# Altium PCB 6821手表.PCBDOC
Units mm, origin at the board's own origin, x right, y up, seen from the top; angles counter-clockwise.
Board outline 79.43 x 61.75 mm, 2 copper layers (Top Layer, Bottom Layer); 27 components, 27 nets, 80 pads, 76 vias.
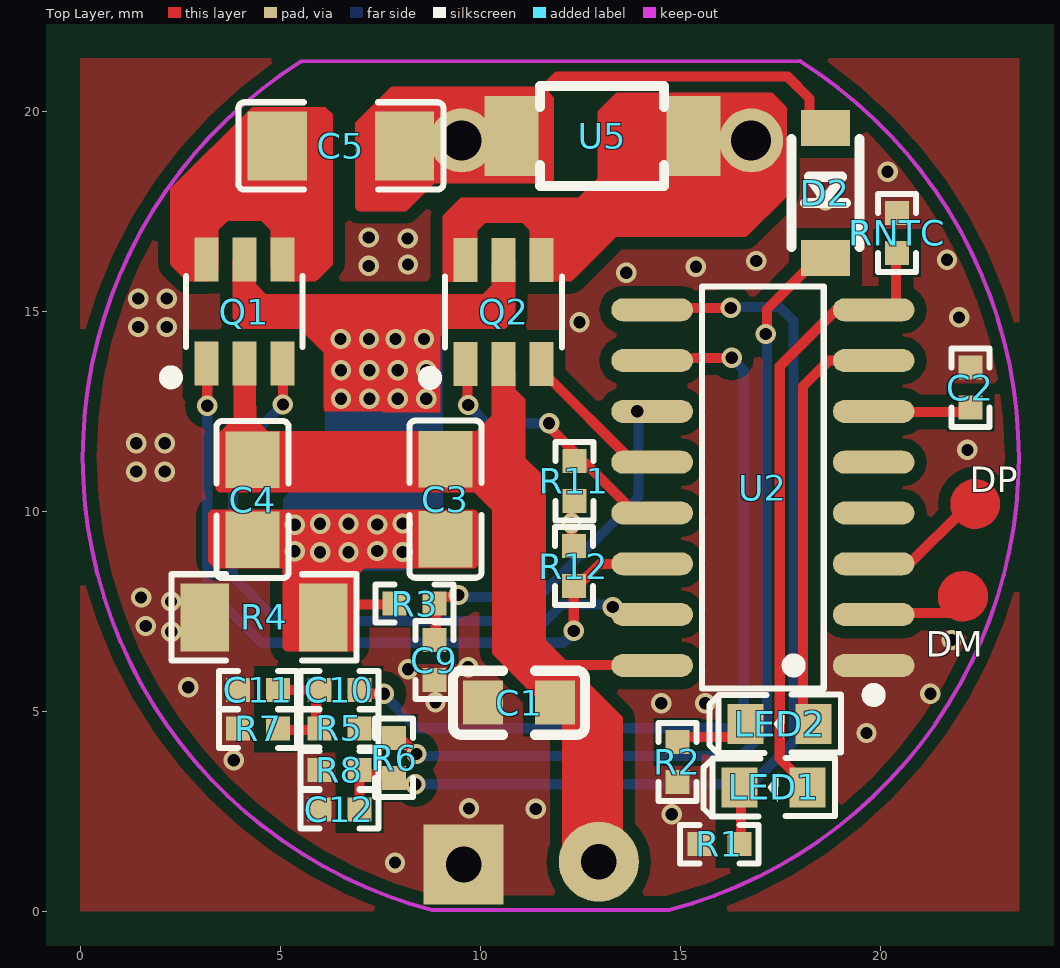
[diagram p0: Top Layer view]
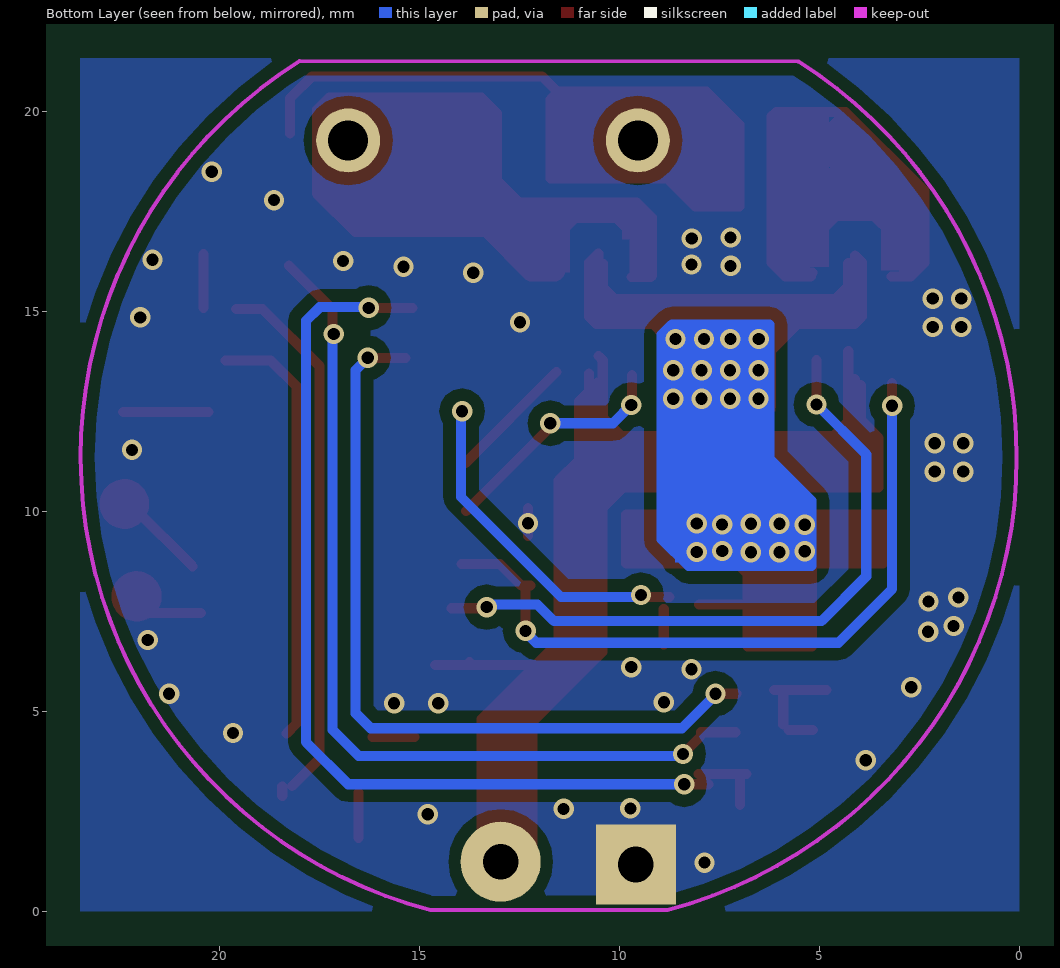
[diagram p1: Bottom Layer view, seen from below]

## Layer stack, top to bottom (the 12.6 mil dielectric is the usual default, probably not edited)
Top Layer: signal copper 0.0356
Dielectric: dielectric 0.32, FR-4, Dk 4.8
Bottom Layer: signal copper 0.0356

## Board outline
55.912,-11.556 -23.514,-11.556 -23.514,50.191 55.912,50.191

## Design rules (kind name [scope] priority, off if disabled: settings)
Clearance [All] p1: gap=0.305
ComponentClearance [All] p1: gap=0.254 collisioncheckmode=3 verticalgap=0.254
PlaneClearance [All] p1: clearance=0
PlaneConnect [All] p1: planeconnectstyle=Direct reliefexpansion=0.508 reliefentries=2 reliefconductorwidth=0.254 reliefairgap=0.254
PolygonConnect [All] p1: connectstyle=Direct reliefconductorwidth=0.254 reliefentries=2 polygonreliefangle="90 Angle"
RoutingVias [All] p1: holewidth=0.711 width=1.27 viastyle="Through Hole" minholewidth=0.711 minwidth=1.27 maxholewidth=0.711 maxwidth=1.27
SolderMaskExpansion [All] p1: expansion=0.102
TestPointUsage [All] p1: valid=0 allowmultiple=FALSE
Testpoint [All] p1: side=15 testpointundercomponent=TRUE minsize=1.016 maxsize=2.54 preferedsize=1.524 minholesize=0 maxholesize=1.016 preferedholesize=0.813 testpointgrid=0.025 style=1023 order=0123456789
Width [All] p1: maxlimit=0.254 minlimit=0.254 preferedwidth=0.254
16 further rules are at their usual default settings.

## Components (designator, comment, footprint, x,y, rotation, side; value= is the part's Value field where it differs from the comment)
C1 "10uF" C0603#1 10.966,5.213 r180 top
C2 "2.2uF" C0603#2 22.251,13.089 r270 top
C3 "22uF" C0805 9.127,10.299 r90 top (schematic designator C9)
C4 "22uF" C0805 4.304,10.289 r90 top (schematic designator C9)
C5 "68nF/NPO" C1206 6.511,19.131 r180 top (schematic designator C11)
C9 "10nF" C0603#2 8.852,6.277 r90 top (schematic designator C12)
C10 "10nF" C0603#2 6.475,5.533 r0 top
C11 "10nF" C0603#2 4.44,5.53 r0 top
C12 "10nF" C0603#2 6.475,2.548 r180 top
D2 "IN5819" SOD-123_L2.7-W1.6-LS3.7-R-RD 18.627,17.955 r90 top
LED1 "R" LED0603_RED 17.328,3.097 r180 top
LED2 "B" LED0603_GREEN 17.478,4.682 r180 top
Q1 "AP10G02" PCBComponent_1#1 4.098,14.992 r0 top
Q2 "AP10G02" PCBComponent_1#1 10.578,14.981 r0 top
R1 "1K" C0603#2 15.972,1.674 r0 top
R2 "1K" C0603#2 14.923,3.732 r90 top
R3 "3.3k" C0603#2 8.355,7.689 r0 top (schematic designator R9)
R4 "20mR" R1206 4.591,7.345 r180 top (schematic designator R10)
R5 "3.3K" C0603#2 6.475,4.57 r0 top
R6 "33K" C0603#2 7.841,3.833 r90 top
R7 "33K" C0603#2 4.44,4.562 r0 top
R8 "3.3k" C0603#2 6.475,3.534 r0 top
R11 "3.3K" C0603#2 12.348,10.749 r90 top
R12 "3.3K" C0603#2 12.337,8.629 r90 top
RNTC "100k/B3950" C0603#2 20.417,16.958 r270 top (schematic designator R1)
U2 "IP6821" SOP-16_L9.9-W3.9-P1.27-LS6.0-BL 17.062,10.59 r90 top (schematic designator U1)
U5 "XianQuan" PCBComponent_1#2 13.051,19.38 r0 top

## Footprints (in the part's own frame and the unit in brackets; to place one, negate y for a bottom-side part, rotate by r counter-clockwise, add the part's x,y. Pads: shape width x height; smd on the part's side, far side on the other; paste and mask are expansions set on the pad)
C0603#1 [mm]
  rect 1x1.1 smd: 1(-0.9,0) 2(0.9,0)
  silkscreen extent -1.65,-0.8 1.65,0.8
C0603#2 [mm]
  rect 0.6x0.6 smd: 1(-0.5,0) 2(0.5,0)
  silkscreen extent -0.98,-0.48 0.98,0.47
C0805 [mm]
  rect 1.41x1.35 smd: 1(-1,0) 2(1,0)
  silkscreen extent -1.96,-0.9 1.96,0.9
C1206 [mm]
  rect 1.485x1.728 smd: 1(-1.593,0) 2(1.592,0)
  silkscreen extent -2.56,-1.09 2.56,1.09
LED0603_GREEN [mm]
  rect 0.9x1 smd: 1(-0.85,0) 2(0.85,0)
  silkscreen extent -1.54,-0.73 1.75,0.73
LED0603_RED [mm]
  rect 0.9x1 smd: 1(-0.85,0) 2(0.85,0)
  silkscreen extent -1.54,-0.73 1.75,0.73
PCBComponent_1#1 [mm]
  rect 0.6x1.1 smd paste+0 mask+0.051: 1(-0.95,-1.3) 2(0,-1.3) 3(0.95,-1.3) 4(0.95,1.3) 5(0,1.3) 6(-0.95,1.3)
  silkscreen extent -1.99,-1.8 1.46,0.89
PCBComponent_1#2 [mm]
  rect 1.35x2 smd: 1(-2.273,0) 2(2.273,0)
  silkscreen extent -1.56,-1.25 1.54,1.25
R1206 [mm]
  rect 1.208x1.701 smd: 1(-1.479,0) 2(1.479,0)
  silkscreen extent -2.31,-1.08 2.31,1.08
SOD-123_L2.7-W1.6-LS3.7-R-RD [mil]
  rect 35.8x48 smd: 1(64,0) 2(-64,0)
  silkscreen extent -53,-33 53,33
SOP-16_L9.9-W3.9-P1.27-LS6.0-BL [mm]
  oval 0.574x2.038 smd paste+0 mask+0.051: 1(-4.445,-2.769) 2(-3.175,-2.769) 3(-1.905,-2.769) 4(-0.635,-2.769) 5(0.635,-2.769) 6(1.905,-2.769) 7(3.175,-2.769) 8(4.445,-2.769) 9(4.445,2.769) 10(3.175,2.769) 11(1.905,2.769) 12(0.635,2.769) 13(-0.635,2.769) 14(-1.905,2.769) 15(-3.175,2.769) 16(-4.445,2.769)
  silkscreen extent -5.33,-2.92 5.03,1.52

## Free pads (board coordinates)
  round 1.6 hole 1: 0(16.771,19.268) 1(9.532,19.268)
  rect 2x2 hole 0.889: 1(9.581,1.167)
  round 2 hole 0.889: 2(12.96,1.237)

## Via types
v1: diameter 0.508, hole 0.305, Top Layer to Bottom Layer, tented both sides, 76 vias

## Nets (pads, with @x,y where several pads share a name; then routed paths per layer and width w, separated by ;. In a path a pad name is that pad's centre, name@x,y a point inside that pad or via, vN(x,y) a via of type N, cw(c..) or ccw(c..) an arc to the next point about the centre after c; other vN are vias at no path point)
CC1: U2.5
CC2: U2.4
D2_2: D2.2 R5.2 R6.2 | length 22.7
  Top Layer w0.254: R5.2@7.087,4.472 R6.2@7.945,4.472 ; R6.2@7.977,4.355 v1(8.4,3.931) ; v1@17.166,14.449 17.166,15.051 D2.2@18.25,16.135
  Bottom Layer w0.254: v1@8.349,4.013 8.482,3.88 16.512,3.88 17.166,4.534 v1@17.166,14.461
  other v1: 17.132,14.429
DBG: 
DM: U2.2 | length 3.4
  Top Layer w0.254: U2.2@20.448,7.453 21.845,7.453
  Top Layer w0.635: 22.376,7.871 ccw(c22.064,7.871) 22.376,7.871
DP: U2.3 | length 4
  Top Layer w0.254: U2.3@20.66,8.62 22.143,10.103
  Top Layer w0.635: 22.672,10.18 ccw(c22.367,10.18) 22.672,10.18
DRV1H: Q2.3 U2.12 | length 3.2
  Top Layer w0.254: Q2.3@11.567,13.479 U2.12@13.842,11.203
DRV1L: Q2.1 R11.2 U2.13 | length 6
  Top Layer w0.254: v1@9.68,12.672 Q2.1@9.68,13.409 ; v1@11.677,12.152 U2.13@13.826,10.002
  Bottom Layer w0.254: v1@9.68,12.672 10.153,12.198 v1(11.718,12.198)
  other v1: 9.695,12.657
DRV2H: Q1.3 U2.15 | length 17
  Top Layer w0.254: v1(5.063,12.666) Q1.3@5.063,13.78 ; v1@13.275,7.575 U2.15@14.192,7.575
  Bottom Layer w0.254: v1(5.063,12.666) 3.818,11.422 3.818,8.372 4.935,7.255 11.63,7.255 12.042,7.666 13.245,7.666 v1(13.31,7.601)
DRV2L: Q1.1 R12.1 U2.14 | length 18.1
  Top Layer w0.254: v1(3.173,12.634) Q1.1@3.173,13.204 ; R12.1@12.211,8.139 12.438,8.139 12.979,8.681 U2.14@13.937,8.681 ; v1(12.335,7.008) R12.1@12.335,8.139
  Bottom Layer w0.254: v1(3.173,12.634) 3.173,8.055 4.515,6.712 12.074,6.712 v1@12.369,7.008
GND: C1.2 C2.1 C9.1 C11.1 C12.2 pad.1@9.581,1.167 R1.1 R2.1 R4.2 R7.1 R8.1 R11.1 R12.2 RNTC.1 U2.1 | length 0.7
  Top Layer w0.254: R12.2@12.276,9.386 R11.1@12.276,10.08
  other v1: 7.865,1.214 14.782,2.423 9.717,2.57 11.385,2.559 3.832,3.773 19.651,4.453 14.519,5.198 15.623,5.198 8.88,5.224 21.249,5.438 2.694,5.6 8.19,6.049 9.693,6.102 21.782,6.778 2.273,6.985 1.635,7.128 2.265,7.74 1.517,7.841 12.276,9.699 1.397,10.989 2.108,10.989 22.175,11.533 1.397,11.7 2.108,11.7 1.446,14.604 2.157,14.604 12.478,14.724 21.969,14.846 1.446,15.315 2.157,15.315 13.644,15.963 15.387,16.113 7.211,16.133 8.189,16.167 16.899,16.257 21.665,16.285 8.181,16.819 7.211,16.844 18.627,17.777 20.181,18.485
ISNS: C9.2 R3.2 U2.11 | length 9.3
  Top Layer w0.254: R3.2@8.747,7.853 v1@9.47,7.853 ; C9.2@8.882,6.674 R3.2@8.882,7.556
  Bottom Layer w0.254: v1@9.422,7.83 9.449,7.856 11.453,7.856 13.953,10.357 v1@13.953,12.5
  other v1: 9.451,7.903 13.924,12.5
LED1: LED1.1 RNTC.2 U2.8 | length 15
  Top Layer w0.254: LED1.1@18.173,3.129 17.485,3.817 17.485,13.625 18.912,15.053 U2.8@19.575,15.053 ; LED1.1@18.418,2.887 LED1.1@18.418,3.116 ; U2.8@20.389,15.076 RNTC.2@20.389,16.428
LED1_2: LED1.2 R1.2 | length 1.1
  Top Layer w0.254: R1.2@16.515,1.828 LED1.2@16.515,2.96
LED2: LED2.1 U2.7 | length 10.8
  Top Layer w0.254: LED2.1@18.311,4.446 18.065,4.691 18.065,13.123 18.707,13.765 U2.7
LED2_2: LED2.2 R2.2 | length 1
  Top Layer w0.254: R2.2@15.118,4.357 16.167,4.357
PGND: C3.1 C4.1 Q1.5 Q2.5 R3.1 R4.1 | length 65.7
  Top Layer w0.254: 4.098,15.002 4.098,16.392 3.928,16.222 3.928,14.864 4.108,14.684 5.533,14.684 6.205,14.012 6.205,12.62 7.398,12.62 ; 4.269,15.627 4.591,15.305 10.109,15.305 10.407,15.602 Q2.5@10.407,16.19 ; Q1.5@4.269,16.201 4.269,15.613 4.322,15.56 4.261,15.436 4.334,15.363 4.429,15.453 4.483,15.399 ; 5.173,8.676 5.173,6.62 6.788,6.62 6.788,8.439 7.023,8.674 ; R4.1@6.097,7.665 R3.1@7.994,7.665 ; 7.686,12.593 8.879,12.593 8.879,14.409 9.151,14.681 10.576,14.681 10.748,14.853 10.748,16.211 10.513,16.446 10.513,15.305 ; 3.322,8.779 3.402,8.7 9.82,8.7 9.82,9.918 3.322,9.918 3.322,8.779
  Bottom Layer w0.254: 5.189,8.629 5.189,10.267 6.238,11.316 6.238,14.666 8.678,14.666 8.932,14.412 8.932,9.297 8.264,8.629 5.189,8.629
  other v1: 5.993,8.974 6.704,8.974 5.355,8.997 7.421,9.004 8.058,8.98 5.358,9.66 5.993,9.685 6.704,9.685 7.423,9.666 8.058,9.692 6.513,12.812 7.224,12.812 7.935,12.812 8.646,12.812 6.513,13.523 7.224,13.523 7.935,13.523 8.646,13.523 6.506,14.305 7.217,14.305 7.877,14.305 8.589,14.305
Q1_5: pad.0 Q2.4 Q2.6 | length 24
  Top Layer w0.254: Q2.6@9.558,15.956 Q2.6@9.568,15.966 ; 9.682,16.945 10.067,17.331 11.091,17.331 11.583,16.839 ; Q2.6@9.683,15.857 9.204,15.857 9.183,15.878 9.183,17.34 9.559,17.716 12.489,17.716 13.051,18.278 13.051,19.954 13.438,20.342 17.247,20.342 17.544,20.044 17.544,17.927 16.598,16.98 13.346,16.98 12.229,15.863 11.572,15.863 Q2.4@11.473,15.963
Q2_5: C5.2 Q1.4 Q1.6 | length 14.6
  Top Layer w0.254: Q1.6@3.191,15.868 2.704,15.868 2.368,16.203 2.368,18.01 4.339,19.982 6.077,19.982 6.186,19.872 6.186,16.211 5.844,15.869 Q1.4@5.2,15.869 ; 3.202,16.957 3.631,17.386 4.568,17.386 5.104,16.85 ; Q1.4@5.162,15.969 Q1.4@5.183,15.948
R3_1: C10.1 C11.2 R5.1 R7.2 | length 2.6
  Top Layer w0.254: C11.2@4.821,5.53 C10.1@6.126,5.53 ; R7.2@5.152,4.534 R5.1@5.761,4.534 ; R5.1@5.896,4.67 C10.1@5.896,5.364
USBC1_A8: 
USBC1_B8: 
VBUS: C1.1 C3.2 C4.2 pad.2 Q1.2 Q2.2 U2.16 | length 57.3
  Top Layer w0.254: 3.553,11.825 10.454,11.825 ; 3.597,11.879 10.537,11.879 ; 3.818,12.045 4.076,12.045 ; Q1.2@3.949,13.148 3.949,12.27 3.51,11.832 3.51,10.594 9.889,10.594 10.417,10.066 10.417,6.484 12.169,4.732 pad.2@12.169,1.238 ; C4.2@4.109,11.883 Q1.2@4.109,13.309 ; Q1.2@4.269,14.004 C4.2@4.271,11.267 ; 9.956,11.885 10.407,12.336 10.407,13.777 Q2.2@10.512,13.882 ; 10.34,11.964 10.604,12.228 10.604,13.119 ; Q2.2@10.512,13.212 Q2.2@10.537,13.212 ; Q2.2@10.749,13.443 10.749,13 11,12.749 11,11.279 11.508,10.771 11.508,6.726 13.437,4.797 13.437,1.719 pad.2@13.667,1.489 ; 11.715,6.157 U2.16@14.595,6.157 ; U2.16@13.738,6.179 U2.16@13.738,6.23
VC: C5.1 D2.1 pad.1@9.532,19.268 | length 22.1
  Top Layer w0.254: 11.532,20.476 11.712,20.296 11.712,18.324 8.8,18.324 8.098,17.622 6.993,17.622 6.993,19.669 7.816,20.493 11.549,20.493 11.928,20.871 17.674,20.871 18.229,20.317 D2.1@18.229,19.439
VCC: C2.2 U2.6 | length 2.1
  Top Layer w0.254: U2.6@20.268,12.482 C2.2@22.405,12.482
VCOIL: C12.1 R6.1 R8.2 U2.9 | length 25.7
  Top Layer w0.254: R8.2@6.819,3.431 R6.1@8.013,3.431 ; C12.1@6.978,2.652 R8.2@6.978,3.371 ; R6.1@7.768,3.172 v1(8.372,3.172) ; U2.9@15.168,15.082 v1(16.26,15.082)
  Bottom Layer w0.254: v1@8.393,3.172 16.772,3.172 17.827,4.227 17.827,14.762 17.486,15.103 16.28,15.103 v1(16.26,15.082)
VDEM: C10.2 U2.10 | length 20
  Top Layer w0.254: C10.2@7.063,5.436 v1(7.59,5.436) ; 15.336,13.834 v1(16.282,13.834)
  Bottom Layer w0.254: v1@7.525,5.376 7.625,5.376 8.425,4.575 16.211,4.575 16.585,4.949 16.585,13.532 v1(16.282,13.834)
pads on no net: U5.1 U5.2

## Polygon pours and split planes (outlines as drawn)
GND on Top Layer "Top Layer-No Net" (solid, pour order 1000): 0,21.32 0,0 15.589,0 23.466,0 23.466,11.58 23.466,21.32 0,21.32
GND on Bottom Layer "Top Layer-No Net" (solid, pour order 1001): 0,0 23.466,0 23.466,21.32 0,21.32

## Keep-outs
Keep-Out Layer:
  lines w0.1: 5.523,21.248 ccw(c11.758,11.348) 8.788,0.031 14.716,0.029 ccw(c11.762,11.348) 17.991,21.249 5.523,21.248

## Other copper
Top Layer:
  region net PGND: 6.192,14.047 6.494,14.35 5.787,15.057 5.485,14.754
  region net PGND: 7.85,14.906 6.084,14.906 6.084,12.496 7.85,12.496
  region net PGND: 7.933,15.346 4.049,15.346 4.049,14.637 7.933,14.637
  rectangle net PGND: 7.749,14.626 10.627,15.412
  rectangle net PGND: 7.562,12.469 9,14.88
  rectangle net Q1_5: 9.66,16.797 9.928,17.214
  region net Q1_5: 9.146,17.205 9.498,16.853 10.105,17.459 9.753,17.812
  region net Q1_5: 9.233,17.468 9.233,15.903 9.743,15.903 9.743,17.468
  region net Q2_5: 4.572,17.766 4.428,17.622 4.878,17.173 5.022,17.316
  region net Q2_5: 4.911,18.577 3.621,18.577 3.621,17.419 4.911,17.419
  region net Q2_5: 3.447,17.964 2.465,17.964 2.465,16.016 3.447,16.016
  rectangle net VC: 6.993,17.622 8.098,18.45
  region net VC: 7.678,18.013 8.098,17.593 8.896,18.391 8.476,18.811
  region net VBUS: 4.166,12.517 3.9,12.251 4.521,11.63 4.787,11.896
  region net VBUS: 10.763,11.479 9.904,10.62 10.681,9.843 11.539,10.702
  region net VBUS: 10.945,12.925 10.551,12.925 10.551,11.737 10.945,11.737
  region net PGND: 6.865,8.874 5.203,8.874 5.203,6.62 6.865,6.62
  region net Q1_5: 13.966,19.822 13.442,20.346 12.977,19.881 13.501,19.357
  region net Q1_5: 14.261,16.894 14.261,17.392 13.292,17.392 13.292,16.894
  rectangle net Q1_5: 13.454,19.187 17.306,20.342
  region net Q1_5: 16.406,19.529 16.773,19.163 17.58,19.969 17.213,20.336
  region net Q1_5: 15.82,17.951 16.694,17.077 17.476,17.858 16.601,18.733
  region net Q1_5: 16.533,20.055 16.533,17.883 17.544,17.883 17.544,20.055
  region net Q1_5: 13.122,19.685 13.122,17.081 16.698,17.081 16.698,19.685
  region net Q1_5: 11.232,17.659 11.232,15.963 12.376,15.963 12.376,17.659
  region net Q1_5: 13.541,18.815 11.512,16.786 12.348,15.95 14.377,17.979
  region net VC: 8.167,19.871 7.681,20.357 6.993,19.669 7.479,19.183
  region net VC: 11.663,18.666 11.663,20.445 7.736,20.445 7.736,18.666
  region net VC: 11.646,18.295 11.646,19.78 6.993,19.78 6.993,18.295
  rectangle net Q2_5: 4.749,16.108 6.125,19.879
  region net Q2_5: 2.377,17.964 3.246,17.095 5.319,19.168 4.45,20.037
  region net PGND: 3.317,9.918 3.317,8.779 9.778,8.779 9.778,9.918
  region net VBUS: 12.169,4.764 12.169,1.237 13.396,1.237 13.396,4.764
  region net VBUS: 11.508,10.721 10.417,10.721 10.417,6.503 11.508,6.503
  region net VBUS: 10.971,10.594 10.971,11.864 3.51,11.864 3.51,10.594
  region net VBUS: 12.794,4.15 13.439,4.795 11.022,7.212 10.377,6.567
  region net VC: 11.436,18.988 10.211,18.988 10.211,18.397 11.436,18.397
  region net Q1_5: 9.649,17.716 9.649,17.292 11.414,17.292 11.414,17.716
  region net Q2_5: 5.218,16.213 5.218,15.909 5.984,15.909 5.984,16.213
  region net Q2_5: 2.636,16.102 2.636,15.901 3.01,15.901 3.01,16.102
Bottom Layer:
  region net PGND: 8.983,9.348 8.317,10.013 7.599,9.294 8.264,8.629
  region net PGND: 6.944,10.708 6.302,11.35 5.137,10.185 5.779,9.543
  region net PGND: 8.597,8.72 8.597,10.061 5.227,10.061 5.227,8.72
  region net PGND: 8.852,9.224 8.852,14.569 6.225,14.569 6.225,9.224

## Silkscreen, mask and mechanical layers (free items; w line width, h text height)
Top Overlay:
  text "DP" at 22.238,10.475 h0.64
  text "DM" at 21.129,6.366 h0.64
Top Solder:
  circle w0.762: c22.362,10.181 r0.373
  circle w0.762: c22.066,7.871 r0.373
